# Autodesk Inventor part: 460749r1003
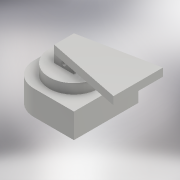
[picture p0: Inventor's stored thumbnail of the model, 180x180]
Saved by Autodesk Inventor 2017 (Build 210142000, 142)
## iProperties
Created: 2016-07
Part Number: 460749r1003
Material: Aluminum 6061
Document SubType Name: Modeling
Designer: Polytech
Density: 2.7 g/cm^3
Appearance: Aluminum - Flat
Mass: 1260.26 g
Surface Area: 611.154 cm^2
Volume: 466.762 cm^3
Author: Polytech
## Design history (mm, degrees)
sketch "Sketch1"
  geometry: C1 r 23 at (0, 0); 1 further point
  constraints: 1 centre point, 1 coincident
  dimensions: "d0" = 46 diameter of C1
extrude "Extrusion1" new body sketch "Sketch1" distance "d1" = 18; taper "d2" = 0 deg
sketch "Sketch2"
  geometry: L1 (48.75, -48.75)-(-11.75, -48.75); L2 (-48.75, -11.75)-(-48.75, 11.75); L3 (-11.75, 48.75)-(48.75, 48.75); L4 (48.75, 48.75)-(48.75, -48.75); L5 (48.75, -48.75)-(-48.75, 48.75); L6 (-48.75, -48.75)-(48.75, 48.75); A1 r 37 centre (-11.75, 11.75) between (-11.75, 48.75) and (-48.75, 11.75); A2 r 37 centre (-11.75, -11.75) between (-48.75, -11.75) and (-11.75, -48.75); 1 further point
  constraints: 12 end point, 4 point on circle, 4 point on line, 4 tangent, 2 centre point, 2 midpoint, 2 parallel, 1 equal radius, 1 horizontal, 1 perpendicular
  dimensions: "d3" = 97.5 distance of L5.end L3.end; "d4" = 97.5 distance of L6.start L5.end; "d5" = 37 radius of A1
extrude "Extrusion2" join sketch "Sketch2" distance "d6" = 37.5; taper "d7" = 0 deg
sketch "Sketch3"
  geometry: C1 r 37.5 at (0, 0); 1 further point
  constraints: 1 centre point, 1 coincident
  dimensions: "d8" = 75 diameter of C1
extrude "Extrusion3" join sketch "Sketch3" distance "d9" = 15; taper "d10" = 0 deg
sketch "Sketch4"
  geometry: L1 (-15, -15)-(15, -15); L2 (15, -15)-(15, 15); L3 (15, 15)-(-15, 15); L4 (-15, 15)-(-15, -15); L5 (-15, -15)-(15, 15); L6 (15, -15)-(-15, 15); 1 further point
  constraints: 12 end point, 2 midpoint, 2 parallel, 1 horizontal, 1 perpendicular
  dimensions: "d11" = 30 distance of L3.end L2.end; "d12" = 30 distance of L2.end L1.end
extrude "Extrusion4" join sketch "Sketch4" distance "d13" = 12; taper "d14" = 0 deg
sketch "Sketch5"
  geometry: L1 (15, 6)-(-15, 6); L2 (-15, 6)-(-15, -6); L3 (-15, -6)-(15, -6); L4 (15, -6)-(15, 6); L5 (15, 6)-(-15, -6); L6 (-15, 6)-(15, -6); 1 further point
  constraints: 12 end point, 2 midpoint, 2 parallel, 1 horizontal, 1 perpendicular
  dimensions: "d15" = 30 distance of L3.end L2.end; "d16" = 12 distance of L2.end L1.end
extrude "Extrusion5" cut sketch "Sketch5" distance "d17" = 12; taper "d18" = 0 deg
sketch "Sketch6"
  geometry: L1 (52.5, 0)-(-22.5, 0) reference; C1 r 3 at (15, 6); 1 further point
  constraints: 1 centre point, 1 vertical alignment
  dimensions: "d19" = 6 diameter of C1; "d20" = 6 distance from line of L1 C1.centre
extrude "Extrusion6" cut sketch "Sketch6" stored distance "d21" = 12; taper "d22" = 0 deg
sketch "Sketch7"
  geometry: L1 (-15, 15)-(-15, -15); L2 (-15, -15)-(97.5, -37.5); L3 (97.5, -37.5)-(97.5, 37.5); L4 (97.5, 37.5)-(-15, 15); 4 further points
  constraints: 8 end point, 2 coincident, 1 horizontal alignment, 1 midpoint, 1 parallel, 1 vertical
  dimensions: "d23" = 75 distance of L2.end L3.end; "d24" = 97.5 distance from line of L3 point (0, 0)
extrude "Extrusion7" join sketch "Sketch7" distance "d25" = 12; taper "d26" = 0 deg
sketch "Sketch8"
  geometry: C1 r 23 at (0, 0); 1 further point
  constraints: 1 centre point, 1 coincident
  dimensions: "d27" = 46 diameter of C1
extrude "Extrusion8" cut sketch "Sketch8" distance "d28" = 24.5; taper "d29" = 0 deg
body "Solid1"
